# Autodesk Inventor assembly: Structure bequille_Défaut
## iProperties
Shininess: 64.0
Length Units: 11269
Angle Units: 11279
Time Units: 11290
Mass Units: 11283
Length Display Precision: 3
Angle Display Precision: 2
Compacted: True
Created: 2006-01
Part Number: Structure bequille_Défaut
Document SubType Name: Assembly
Designer: Fricot
Density: 0.0
Volumn: 0.0
Area: 0.0
PropertySet Name: Model Information
Control State: 0
Master: False
Checked Out: False
Author: Fricot
